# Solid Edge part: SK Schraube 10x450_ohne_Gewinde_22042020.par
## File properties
Author: fknapp
Template: Normal.par
Last saved by: fknapp
Revision: 33
Application: Solid Edge
Username: fknapp
Material: Aluminium
Genauigkeit: 0,99
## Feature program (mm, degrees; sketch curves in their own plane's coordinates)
sketch for "unnamed RevolvedProtrusion 1" plane through (0, 0, 0) normal (0, 0, 1) x-axis (1, 0, 0)
  line (0, 54) -> (9, 54)
  line (9, 54) -> (9, 53)
  line (9, 53) -> (5, 49)
  line (5, 49) -> (5, 46.3)
  line (5, 46.3) -> (4.7548, 46.3)
  arc centre (4.7548, 44.6952) radius 1.6048 from (4.7548, 46.3) to (3.15, 44.6952) ccw
  line (3.15, 44.6952) -> (3.15, 42)
  line (3.15, 42) -> (5, 42)
  line (5, -383) -> (5, 42)
  line (0.5, -396) -> (5, -383)
  line (0, -396) -> (0.5, -396)
revolve "unnamed RevolvedProtrusion 1" add full turn 360 deg about sketch line (0, 54) -> (0, -396)
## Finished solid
Body 1: solid body, 11 faces, 10 edges, 0 vertices.
  Faces by surface: cylinder 4, plane 4, cone 2, torus 1
  Edges by curve: circle 10
Bounding box of the edges (mm; curved faces can reach further): 18.000 x 450.000 x 18.000, from (-9, -396, -9) to (9, 54, 9).
Cylindrical faces by radius (mm): R3.15 x1, R5 x2, R9 x1
Conical faces (half-angle, radius in mm at the cone's reference point): 19.0935 deg R5 x1, 45 deg R9 x1
Toroidal faces (ring radius, tube radius in mm): R4.7548 r1.6048 x1
Planar faces by outward normal: +y 2, -y 2
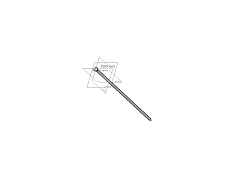
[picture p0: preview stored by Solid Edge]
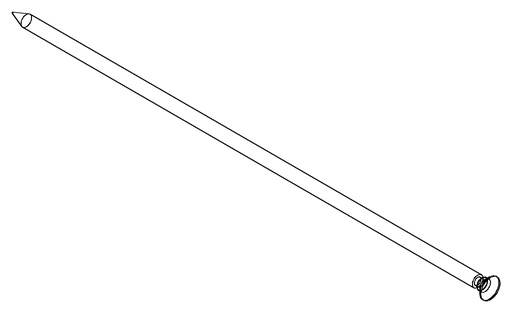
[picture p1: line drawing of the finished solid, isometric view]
